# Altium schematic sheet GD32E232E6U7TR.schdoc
size 127 x 101 mm
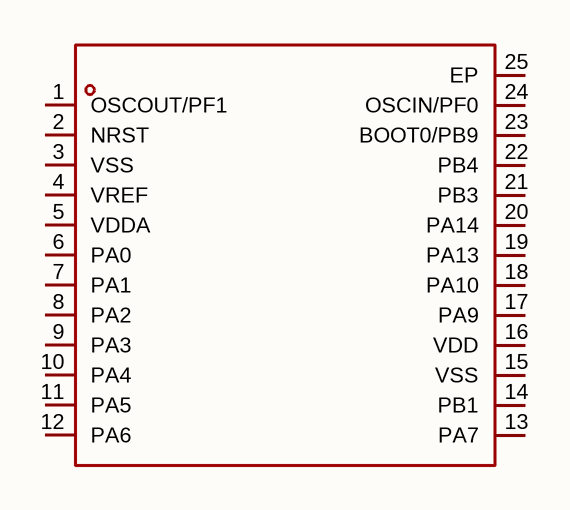
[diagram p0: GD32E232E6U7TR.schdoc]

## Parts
U?  gd32e232e6u7tr  [QFN-24_L3.0-W3.0-P0.40-BL-EP1.7]  (value not drawn)

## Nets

Not connected (* = marked no-connect by the designer): U? 1(OSCOUT/PF1) 2(NRST) 3(VSS) 4(VREF) 5(VDDA) 6(PA0) 7(PA1) 8(PA2) 9(PA3) 10(PA4) 11(PA5) 12(PA6) 13(PA7) 14(PB1) 15(VSS) 16(VDD) 17(PA9) 18(PA10) 19(PA13) 20(PA14) 21(PB3) 22(PB4) 23(BOOT0/PB9) 24(OSCIN/PF0) 25(EP)

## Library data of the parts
U? = gd32e232e6u7tr: CPU内核:ARM Cortex-M系列;CPU最大主频:72MHz;; Manufacturer: GigaDevice(兆易创新); AddInBom: yes; ModelId: b6b6aa71436d40c48e76c43474c53447; ModelName: QFN-24_L3.0-W3.0-H0.9-P0.40-BL-EP1.7; ModelTransform: 118.11,118.11,0,90,0,0,0.002,-0.003,0; CPU Maximum Speed: 72MHz; Program Storage Size: 32KB; Program Memory Type: FLASH; Number of I/O: 18; ADC (Bit): 12bit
